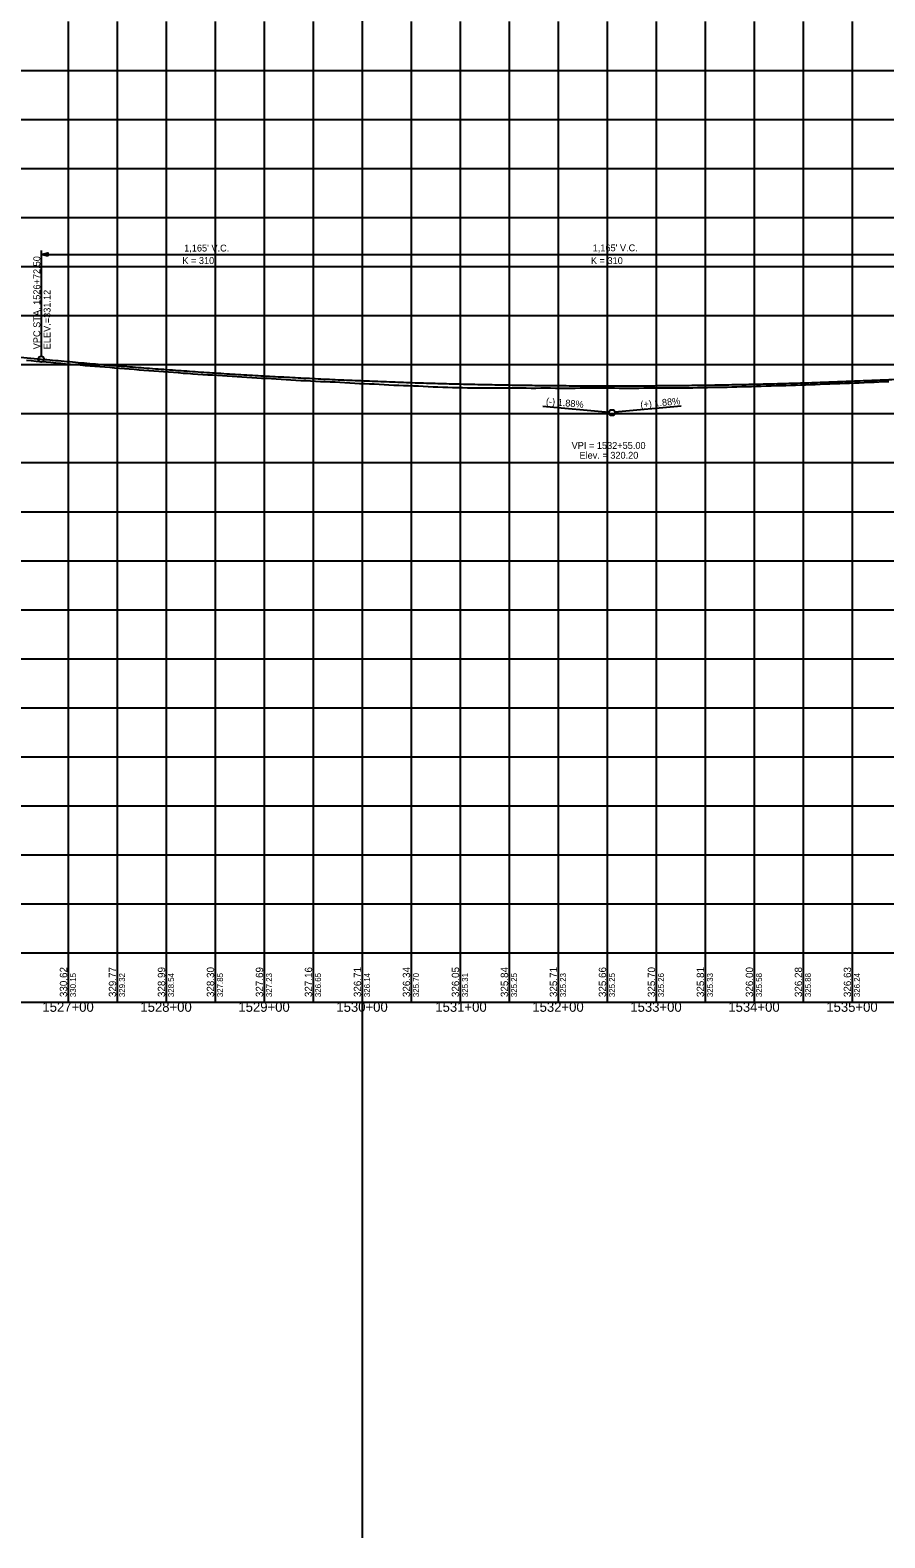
# Model space of a CAD drawing. Extents: x -90830 to 2015517, y -20856 to 836331.
# Drawn here: x 41585 to 42457, y -11344 to -9806 of the extents above; entities that cross this region are included whole.
import ezdxf

# ---------------------------------------------------------------- set-up
doc = ezdxf.new("R2010")
doc.units = 0
for name, color, linetype in [('Level 1', 7, 'Continuous'), ('RD_DDB_GradeTX', 7, 'Continuous'), ('RD_DDB_Profile_Elev', 7, 'Continuous'), ('RD_DDB_Profile_EX', 7, 'Continuous'), ('RD_DDB_Profile_Lbl', 7, 'Continuous'), ('RD_DDB_Profile_PR', 7, 'Continuous'), ('RD_DDB_StaTX', 7, 'Continuous'), ('RD_DDB_StripGrade', 7, 'Continuous'), ('RD_DDB_VCLbl', 7, 'Continuous'), ('RD_GPK_Profile_Cell', 7, 'Continuous'), ('RD_PD_Final_TX', 7, 'Continuous')]:
    doc.layers.add(name, color=color, linetype=linetype)

msp = doc.modelspace()

# ---------------------------------------------------------------- linework, layer by layer
at = {"layer": 'Level 1'}
for p, q in [((41923.5, -3180.8), (41923.5, -11343.5)), ((41623.5, -9797.1), (41623.5, -10297.1)), ((41673.5, -9797.1), (41673.5, -10297.1)), ((41723.5, -9797.1), (41723.5, -10297.1)), ((41773.5, -9797.1), (41773.5, -10297.1)), ((41823.5, -9797.1), (41823.5, -10297.1)), ((41873.5, -9797.1), (41873.5, -10297.1)), ((41923.5, -9797.1), (41923.5, -10297.1)), ((41973.5, -9797.1), (41973.5, -10297.1)), ((42023.5, -9797.1), (42023.5, -10297.1)), ((42073.5, -9797.1), (42073.5, -10297.1)), ((42123.5, -9797.1), (42123.5, -10297.1)), ((42173.5, -9797.1), (42173.5, -10297.1)), ((42223.5, -9797.1), (42223.5, -10297.1)), ((42273.5, -9797.1), (42273.5, -10297.1)), ((42323.5, -9797.1), (42323.5, -10297.1)), ((42373.5, -9797.1), (42373.5, -10297.1)), ((42423.5, -9797.1), (42423.5, -10297.1)), ((41573.5, -9847.1), (43173.5, -9847.1)), ((41573.5, -9897.1), (43173.5, -9897.1)), ((41573.5, -9947.1), (43173.5, -9947.1)), ((41573.5, -9997.1), (43173.5, -9997.1)), ((41573.5, -10047.1), (43173.5, -10047.1)), ((41573.5, -10097.1), (43173.5, -10097.1)), ((41573.5, -10147.1), (43173.5, -10147.1)), ((41573.5, -10197.1), (43173.5, -10197.1)), ((41573.5, -10247.1), (43173.5, -10247.1)), ((41573.5, -10297.1), (43173.5, -10297.1)), ((41573.5, -10297.1), (43173.5, -10297.1)), ((41623.5, -10297.1), (41623.5, -10797.1)), ((41673.5, -10297.1), (41673.5, -10797.1)), ((41723.5, -10297.1), (41723.5, -10797.1)), ((41773.5, -10297.1), (41773.5, -10797.1)), ((41823.5, -10297.1), (41823.5, -10797.1)), ((41873.5, -10297.1), (41873.5, -10797.1)), ((41923.5, -10297.1), (41923.5, -10797.1)), ((41973.5, -10297.1), (41973.5, -10797.1)), ((42023.5, -10297.1), (42023.5, -10797.1)), ((42073.5, -10297.1), (42073.5, -10797.1)), ((42123.5, -10297.1), (42123.5, -10797.1)), ((42173.5, -10297.1), (42173.5, -10797.1)), ((42223.5, -10297.1), (42223.5, -10797.1)), ((42273.5, -10297.1), (42273.5, -10797.1)), ((42323.5, -10297.1), (42323.5, -10797.1)), ((42373.5, -10297.1), (42373.5, -10797.1)), ((42423.5, -10297.1), (42423.5, -10797.1)), ((41573.5, -10347.1), (43173.5, -10347.1)), ((41573.5, -10397.1), (43173.5, -10397.1)), ((41573.5, -10447.1), (43173.5, -10447.1)), ((41573.5, -10497.1), (43173.5, -10497.1)), ((41573.5, -10547.1), (43173.5, -10547.1)), ((41573.5, -10597.1), (43173.5, -10597.1)), ((41573.5, -10647.1), (43173.5, -10647.1)), ((41573.5, -10697.1), (43173.5, -10697.1)), ((41573.5, -10747.1), (43173.5, -10747.1)), ((41573.5, -10797.1), (43173.5, -10797.1))]:
    msp.add_line(p, q, dxfattribs=at)
at = {"layer": 'RD_DDB_GradeTX'}
for p, q in [((42107.8, -10189.5), (42175.5, -10195.8)), ((42249.1, -10189.5), (42181.4, -10195.8))]:
    msp.add_line(p, q, dxfattribs=at)
msp.add_circle((42178.5, -10196.1), 3, dxfattribs=at)
at = {"layer": 'RD_DDB_Profile_EX'}
for points in [[(41580.9, -10142.6), (41585.9, -10143.1), (41590.9, -10143.5), (41595.9, -10144), (41600.9, -10144.4), (41605.9, -10144.8), (41610.9, -10145.3), (41615.9, -10145.7), (41620.9, -10146.2), (41625.9, -10146.6), (41630.9, -10147.1), (41635.9, -10147.5), (41640.9, -10147.9), (41645.9, -10148.3), (41650.9, -10148.7), (41655.9, -10149.1), (41660.9, -10149.5), (41665.9, -10149.9), (41670.9, -10150.3), (41675.9, -10150.7), (41680.9, -10151.1), (41685.9, -10151.5), (41690.9, -10151.9), (41695.9, -10152.4), (41700.9, -10152.7), (41705.9, -10153.1), (41710.9, -10153.5), (41715.9, -10153.9), (41720.9, -10154.2), (41725.9, -10154.6), (41730.9, -10154.9), (41735.9, -10155.3), (41740.9, -10155.7), (41745.9, -10156), (41750.9, -10156.4), (41755.9, -10156.8), (41760.9, -10157.1), (41765.9, -10157.4), (41770.9, -10157.7), (41775.9, -10158), (41780.9, -10158.3), (41785.9, -10158.6), (41790.9, -10158.9), (41795.9, -10159.2), (41800.9, -10159.5), (41805.9, -10159.9), (41810.9, -10160.2), (41815.9, -10160.5), (41820.9, -10160.8), (41825.9, -10161.1), (41830.9, -10161.4), (41835.9, -10161.7), (41840.9, -10162), (41845.9, -10162.4), (41850.9, -10162.7), (41855.9, -10163), (41860.9, -10163.3), (41865.9, -10163.5), (41870.9, -10163.8), (41875.9, -10164), (41880.9, -10164.2), (41885.9, -10164.4), (41890.9, -10164.6), (41895.9, -10164.8), (41900.9, -10165.1), (41905.9, -10165.5), (41910.9, -10165.8), (41915.9, -10166.1), (41920.9, -10166.3)], [(41920.9, -10166.3), (41925.9, -10166.5), (41930.9, -10166.7), (41935.9, -10166.9), (41940.9, -10167.2), (41945.9, -10167.5), (41950.9, -10167.8), (41955.9, -10168), (41960.9, -10168.2), (41965.9, -10168.4), (41970.9, -10168.5), (41975.9, -10168.7), (41980.9, -10168.9), (41985.9, -10169.2), (41990.9, -10169.4), (41995.9, -10169.7), (42000.9, -10169.9), (42005.9, -10170.1), (42010.9, -10170.3), (42015.9, -10170.5), (42020.9, -10170.5), (42025.9, -10170.6), (42030.9, -10170.7), (42035.9, -10170.7), (42040.9, -10170.8), (42045.9, -10170.8), (42050.9, -10170.9), (42055.9, -10170.9), (42060.9, -10170.9), (42065.9, -10170.9), (42070.9, -10170.9), (42075.9, -10170.9), (42080.9, -10170.9), (42085.9, -10170.9), (42090.9, -10170.9), (42095.9, -10171), (42100.9, -10171), (42105.9, -10170.9), (42110.9, -10170.9), (42115.9, -10170.9), (42120.9, -10171), (42125.9, -10171), (42130.9, -10171), (42135.9, -10171), (42140.9, -10171), (42145.9, -10170.9), (42150.9, -10170.8), (42155.9, -10170.8), (42160.9, -10170.8), (42165.9, -10170.8), (42170.9, -10170.8), (42175.9, -10170.9), (42180.9, -10170.9), (42185.9, -10171), (42190.9, -10171.1), (42195.9, -10171.1), (42200.9, -10171), (42205.9, -10171), (42210.9, -10170.9), (42215.9, -10170.9), (42220.9, -10170.9), (42225.9, -10170.8), (42230.9, -10170.8), (42235.9, -10170.7), (42240.9, -10170.8), (42245.9, -10170.8), (42250.9, -10170.8), (42255.9, -10170.8), (42260.9, -10170.7), (42265.9, -10170.6), (42270.9, -10170.5), (42275.9, -10170.4), (42280.9, -10170.3), (42285.9, -10170.2), (42290.9, -10170.1), (42295.9, -10170), (42300.9, -10169.8), (42305.9, -10169.7), (42310.9, -10169.6), (42315.9, -10169.4), (42320.9, -10169.3), (42325.9, -10169.1), (42330.9, -10169), (42335.9, -10168.9), (42340.9, -10168.8), (42345.9, -10168.6), (42350.9, -10168.5), (42355.9, -10168.4), (42360.9, -10168.2), (42365.9, -10168), (42370.9, -10167.8), (42375.9, -10167.6), (42380.9, -10167.4), (42385.9, -10167.3), (42390.9, -10167.1), (42395.9, -10166.9), (42400.9, -10166.7), (42405.9, -10166.5), (42410.9, -10166.4), (42415.9, -10166.2), (42420.9, -10166)], [(42420.9, -10166), (42425.9, -10165.8), (42430.9, -10165.6), (42435.9, -10165.4), (42440.9, -10165.2), (42445.9, -10165), (42450.9, -10164.8), (42455.9, -10164.5), (42460.9, -10164.3)]]:
    msp.add_lwpolyline(points, dxfattribs=at)
at = {"layer": 'RD_DDB_Profile_PR'}
msp.add_line((40816, -10068.4), (41596, -10141.5), dxfattribs=at)
msp.add_spline([(41596, -10141.5), (41619.3, -10143.6), (41642.6, -10145.7), (41665.9, -10147.7), (41689.2, -10149.5), (41712.5, -10151.3), (41735.8, -10153), (41759.1, -10154.7), (41782.4, -10156.2), (41805.7, -10157.6), (41829, -10159), (41852.3, -10160.2), (41875.6, -10161.4), (41898.9, -10162.5), (41922.2, -10163.5), (41945.5, -10164.4), (41968.8, -10165.3), (41992.1, -10166), (42015.4, -10166.7), (42038.7, -10167.2), (42062, -10167.7), (42085.3, -10168.1), (42108.6, -10168.4), (42131.9, -10168.6), (42155.2, -10168.8), (42178.5, -10168.8), (42201.8, -10168.8), (42225.1, -10168.6), (42248.4, -10168.4), (42271.7, -10168.1), (42295, -10167.7), (42318.3, -10167.2), (42341.6, -10166.7), (42364.9, -10166), (42388.2, -10165.3), (42411.5, -10164.4), (42434.8, -10163.5), (42458.1, -10162.5), (42481.4, -10161.4), (42504.7, -10160.2), (42528, -10159), (42551.3, -10157.6), (42574.6, -10156.2), (42597.9, -10154.6), (42621.2, -10153), (42644.5, -10151.3), (42667.8, -10149.5), (42691.1, -10147.6), (42714.4, -10145.7), (42737.7, -10143.6), (42761, -10141.5)], degree=3, dxfattribs=at)
at = {"layer": 'RD_DDB_VCLbl'}
for p, q in [((41596, -10030.9), (41596, -10138.5)), ((41596, -10035), (42761, -10035))]:
    msp.add_line(p, q, dxfattribs=at)
msp.add_circle((41596, -10141.5), 3, dxfattribs=at)
at = {"layer": 'RD_GPK_Profile_Cell'}
msp.add_line((4823.5, -10797.1), (75223.5, -10797.1), dxfattribs=at)
at = {"layer": 'RD_PD_Final_TX'}
msp.add_lwpolyline([(41602.6, -10036.6), (41596, -10035), (41602.6, -10033.3)], close=True, dxfattribs=at)

# ---------------------------------------------------------------- texts
at = {"layer": 'RD_DDB_GradeTX'}
for s, rotation, p in [('(-) 1.88%', 354.6431, (42110.9, -10187.8)), ('(+) 1.88%', 5.362, (42207.8, -10191.4))]:
    msp.add_text(s, height=7, rotation=rotation, dxfattribs=at).set_placement(p)
at = {"layer": 'RD_DDB_Profile_Elev'}
for s, p in [('330.62', (41622.5, -10792.1)), ('329.77', (41672.5, -10792.1)), ('328.99', (41722.5, -10792.1)), ('328.30', (41772.5, -10792.1)), ('327.69', (41822.5, -10792.1)), ('327.16', (41872.5, -10792.1)), ('326.71', (41922.5, -10792.1)), ('326.34', (41972.5, -10792.1)), ('326.05', (42022.5, -10792.1)), ('325.84', (42072.5, -10792.1)), ('325.71', (42122.5, -10792.1)), ('325.66', (42172.5, -10792.1)), ('325.70', (42222.5, -10792.1)), ('325.81', (42272.5, -10792.1)), ('326.00', (42322.5, -10792.1)), ('326.28', (42372.5, -10792.1)), ('326.63', (42422.5, -10792.1))]:
    msp.add_text(s, height=7.5, rotation=90, dxfattribs=at).set_placement(p)
at = {"layer": 'RD_DDB_Profile_Lbl'}
for s, p in [('VPI = 1532+55.00', (42137.3, -10233.1)), ('Elev. = 320.20', (42145.3, -10243.1))]:
    msp.add_text(s, height=7, dxfattribs=at).set_placement(p)
at = {"layer": 'RD_DDB_StaTX'}
for s, p in [('1527+00', (41597.2, -10807.1)), ('1528+00', (41697.2, -10807.1)), ('1529+00', (41797.2, -10807.1)), ('1530+00', (41897.2, -10807.1)), ('1531+00', (41998.2, -10807.1)), ('1532+00', (42097.2, -10807.1)), ('1533+00', (42197.2, -10807.1)), ('1534+00', (42297.2, -10807.1)), ('1535+00', (42397.2, -10807.1))]:
    msp.add_text(s, height=10, dxfattribs=at).set_placement(p)
at = {"layer": 'RD_DDB_StripGrade'}
for s, height, p in [('VPC STA. 1526+72.50 ', 7, (41595, -10131.5)), ('ELEV.=331.12', 7, (41605.5, -10131.5)), ('330.15', 6, (41631.5, -10792.1)), ('329.32', 6, (41681.5, -10792.1)), ('328.54', 6, (41731.5, -10792.1)), ('327.85', 6, (41781.5, -10792.1)), ('327.23', 6, (41831.5, -10792.1)), ('326.65', 6, (41881.5, -10792.1)), ('326.14', 6, (41931.5, -10792.1)), ('325.70', 6, (41981.5, -10792.1)), ('325.31', 6, (42031.5, -10792.1)), ('325.25', 6, (42081.5, -10792.1)), ('325.23', 6, (42131.5, -10792.1)), ('325.25', 6, (42181.5, -10792.1)), ('325.26', 6, (42231.5, -10792.1)), ('325.33', 6, (42281.5, -10792.1)), ('325.58', 6, (42331.5, -10792.1)), ('325.88', 6, (42381.5, -10792.1)), ('326.24', 6, (42431.5, -10792.1))]:
    msp.add_text(s, height=height, rotation=90, dxfattribs=at).set_placement(p)
at = {"layer": 'RD_DDB_VCLbl'}
for s, p in [('K = 310', (41740, -10044.5)), ("1,165' V.C.", (41741.9, -10031.8)), ('K = 310', (42157, -10044.6)), ("1,165' V.C.", (42158.8, -10031.6))]:
    msp.add_text(s, height=7, dxfattribs=at).set_placement(p)

doc.saveas('drawing.dxf')
